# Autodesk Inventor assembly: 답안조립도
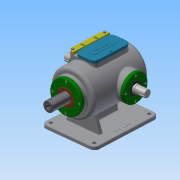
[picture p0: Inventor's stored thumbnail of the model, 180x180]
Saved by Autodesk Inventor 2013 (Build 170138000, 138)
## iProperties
Created: 2018-08
Part Number: 답안조립도
Document SubType Name: Assembly
Designer: Administrator
Author: Administrator
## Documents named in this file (15)
- C:\Users\Administrator\Desktop\380808V1023\공용부품_20180825_1\답안조립도.iam
- C:\Users\Administrator\Desktop\380808V1023\공용부품_20180825_1\본체.ipt
- C:\Users\Administrator\Desktop\380808V1023\공용부품_20180825_1\편심축.ipt
- C:\Users\Administrator\Desktop\380808V1023\공용부품_20180825_1\베어링 6205.ipt
- 베어링 6205.ipt
- C:\Users\Administrator\Desktop\380808V1023\공용부품_20180825_1\축 커버.ipt
- C:\Users\Administrator\Desktop\380808V1023\공용부품_20180825_1\오일 실 25 38 8.ipt
- C:\Users\Administrator\Desktop\380808V1023\공용부품_20180825_1\슬라이드.ipt
- C:\Users\Administrator\Desktop\380808V1023\공용부품_20180825_1\슬라이드 커버.ipt
- C:\Users\Administrator\Desktop\380808V1023\공용부품_20180825_1\부시.ipt
- C:\Users\Administrator\Desktop\380808V1023\공용부품_20180825_1\상부커버.ipt
- C:\Users\Administrator\Desktop\380808V1023\공용부품_20180825_1\고정플레이트.ipt
- C:\Users\Administrator\Desktop\380808V1023\공용부품_20180825_1\볼트 M4x0.7.ipt
- C:\Users\Administrator\Desktop\380808V1023\공용부품_20180825_1\육각머리볼트 M4.ipt
- C:\Users\Administrator\Desktop\380808V1023\공용부품_20180825_1\가변스프링.ipt
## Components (14 placed, 3 different names)
1. 고정플레이트:1
2. M4x0.7:1
3. M4x0.7:2
4. M4x0.7:3
5. M4x0.7:4
6. M4x0.7:5
7. M4x0.7:6
8. M4x0.7:7
9. M4x0.7:8
10. M4x0.7:9
11. M4x0.7:10
12. M4x0.7:11
13. M4x0.7:12
14. 가변스프링:1
